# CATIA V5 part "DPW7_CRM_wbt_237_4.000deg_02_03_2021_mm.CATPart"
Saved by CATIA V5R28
Part number: DPW7_CRM_wbt_237_4.006deg_02_03_2021
Bounding box of the stored display mesh (mm): x 2349.5 to 66711.891, y 0 to 29555.555, z 2310.119 to 8715.756
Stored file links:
  Z:\Scratch\04_CAD_Allgemein\Flight2Jig\Output\DPW-7\CATPart\DPW7_CRM_wbt_237_4.006deg_02_03_2021.CATPart
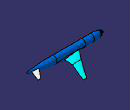
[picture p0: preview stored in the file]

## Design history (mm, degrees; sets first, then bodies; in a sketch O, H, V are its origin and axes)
Set1
  DatumSurface1 "Clean_Wing"
  DatumSurface2 "Fuselage"
  DatumSurface3 "HTP"
  DatumSurface4 "Symmetry"
  DatumSurface5 "Farfield"
Body1 (main body)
